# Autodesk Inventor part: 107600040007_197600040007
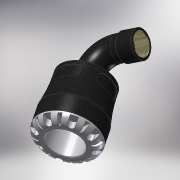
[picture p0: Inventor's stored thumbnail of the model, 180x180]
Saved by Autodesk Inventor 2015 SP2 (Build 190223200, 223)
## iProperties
Created: 2016-12
Part Number: 107600040007_197600040007
Material: PVC-Piping
Description: PLASSON 90° ELBOW WITH FEMALE INTEGRAL BRASS THREAD 40X3/4" SERIES 1
Document SubType Name: Modeling
Designer: KIM
Mass: 664.223 g
Surface Area: 733.008 cm^2
Volume: 474.445 cm^3
Density: 1.4 g/cm^3
Appearance: Black Cast
Author: KIM
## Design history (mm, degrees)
derived "1076.ipt"
feature "Solid1::1076.ipt"
tag "TaggingFeature1"
body "Solid1"
other parameters: "d1" = 30.24, "d8" = 61.6, "d13" = 8, "d14" = 8, "d15" = 0, "d17" = 360 deg, "d19" = 8 deg, "d20" = 0.8, "d21" = 0.8, "d22" = 8 deg, "d24" = 0, "d26" = 360 deg, "d33" = 7, "d51" = 0.7, "d54" = 14, "d55" = 8.8, "d57" = 15.68, "d58" = 0, "d74" = 0, "d78" = 72, "d82" = 0.8, "d115" = 360 deg, "d207" = 90 deg, "d228" = 11.9, "d248" = 4.32, "d270" = 107, "d279" = 51, "d281" = 3.61755, "d294" = 24.117, "d295" = 16, "d296" = 17.6, "d297" = 21.7053, "d299" = 28.21689, "d300" = 21.7053, "d301" = 0, "d302" = 0, "d306" = 1.5676, "d309" = 72.72, "d310" = 16.69156, "d312" = 15 deg, "d313" = 0.56, "d314" = 8.208, "d315" = 0.35, "l_" = 72, "A_" = 107, "A_1" = 51, "l_2" = 16, "Rp_" = 24.117, "d298" = 31.3521
